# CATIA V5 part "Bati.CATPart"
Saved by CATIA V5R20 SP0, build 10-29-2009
Part number: Bati
Bounding box of the stored display mesh (mm): x -25 to 40, y -32.207 to 205.154, z -45 to 78
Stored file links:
  D:\Dropbox\IAO_2011\MMS_GR2\IAO_2011_1495_fpittorino\fpittorino_IAO\IAO_2011_1495_fpittorino\Bati.CATPart
  D:\Dropbox\IAO_2011\MMS_GR2\IAO_2011_1495_fpittorino\fpittorino_IAO\IAO_2011_1495_fpittorino\Product3.CATProduct
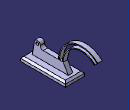
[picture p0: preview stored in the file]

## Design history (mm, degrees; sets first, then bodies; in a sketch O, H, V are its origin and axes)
External parameters (linked from other documents)
  External.Angle_glissiere = 45 deg
  External.L3 = 70 mm
Set1
  Plane1: linked copy from another document
  Point1: linked copy from another document
  Line1: linked copy from another document
  Point2 to Point4: linked copy from another document
Body1 (main body)
  Sketch1 on Plane1, origin (0, 0, 10), H (0, 1, 0), V (0, 0, 1)
    arc A1 centre (0, 0) radius 10 from (10, 0) to (-9.8481, 1.7365) ccw
    point P1 (10, 0)
    point P3 (88, -10)
    arc A2 centre (20, 0) radius 10 from (20, -10) to (10, 0) cw
    point P6 (10, 0)
    line L1 (-9.8481, 1.7365) -> (-17.2073, -40)
    line L2 (-17.2073, -40) -> (105.3205, -40)
    line L3 (88, -10) -> (105.3205, -40)
    circle A3 centre (0, 0) radius 5
    point P9 (150, -10)
    point P10 (80, -10)
    reference projected point E1 (150, -10) from Point2
    axis line L4 (150, -10) -> (185.3555, 25.3555)
    reference projected line E2 (150, -10) -> (0, -10) from Line1
    arc A4 centre (150, -10) radius 65 from (195.9619, 35.9619) to (85, -10) ccw
    point P12 (85, -10)
    point P13 (195.9619, 35.9619)
    arc A5 centre (150, -10) radius 75 from (203.033, 43.033) to (75, -10) ccw
    point P14 (75, -10)
    point P15 (203.033, 43.033)
    reference projected point E3 (150, -10) from Point4
    arc A6 centre (150, -10) radius 62 from (193.8406, 33.8406) to (88, -10) ccw
    point P16 (193.8406, 33.8406)
    arc A7 centre (150, -10) radius 78 from (205.1543, 45.1543) to (72, -10) ccw
    point P17 (72, -10)
    point P18 (205.1543, 45.1543)
    line L5 (193.8406, 33.8406) -> (195.9619, 35.9619)
    point P19 (193.8406, 33.8406)
    line L6 (203.033, 43.033) -> (205.1543, 45.1543)
    line L7 (85, -10) -> (75, -10)
    line L8 (72, -10) -> (20, -10)
    radius A3 = 5
    radius A1 = 10
    angle L1 L2 = 80
    angle L3 L2 = 60
    angle L4 E2 = 45 {= External.Angle_glissiere}
    distance P12 P10 = 5
    distance P10 P14 = 5
    distance P3 E3 = 62 {= External.L3 -8mm}
    distance P12 P3 = 3
    distance P17 P14 = 3
    radius A2 = 10
    coincidence: P1 H, A2 P1, P6 A1, P6 P1, P9 E1, P13 L4, P15 L4, P16 L4, P18 L4, P19 L4, L7 L8, P16 P19
    tangency: A1 A2, L1 A1, L7 A1, L8 A1, L8 A2
    parallelism: L5 L4, L6 L4, L2 L8
  Pad1: profile Sketch1, direction (1, 0, 0), length 15
  Sketch2 on face of Pad1 from Sketch1.L2, origin (0, 0, -30), H (1, 0, 0), V (0, -1, 0)
    line L1 (-25, 32.2073) -> (40, 32.2073)
    line L2 (40, 32.2073) -> (40, -120.3205)
    line L3 (40, -120.3205) -> (-25, -120.3205)
    line L4 (-25, -120.3205) -> (-25, 32.2073)
    reference projected line E1 (15, 17.2073) -> (15, -125.3205) from edge [face of Pad1 from Sketch1.L2 | end face of Pad1]
    reference projected line E2 (0, 17.2073) -> (0, -125.3205) from edge [start face of Pad1 | face of Pad1 from Sketch1.L2]
    reference projected line E3 (0, -105.3205) -> (15, -105.3205) from edge [face of Pad1 from Sketch1.L3 | face of Pad1 from Sketch1.L2]
    reference projected line E4 (0, 17.2073) -> (15, 17.2073) from edge [face of Pad1 from Sketch1.L2 | face of Pad1 from Sketch1.L1]
    distance L2 E1 = 25
    distance E2 L4 = 25
    distance E3 L3 = 15
    distance L1 E4 = 15
    horizontal: L1 H, L3 H
    vertical: L2 V, L4 V
  Pad2: profile Sketch2, direction (0, 0, -1), length 15
  Chamfer1: length 6, angle 45, on edge [start face of Pad2 | face of Pad2 from Sketch2.L2]; edge [start face of Pad2 | face of Pad2 from Sketch2.L1]; edge [start face of Pad2 | face of Pad2 from Sketch2.L4]; edge [start face of Pad2 | face of Pad2 from Sketch2.L3]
